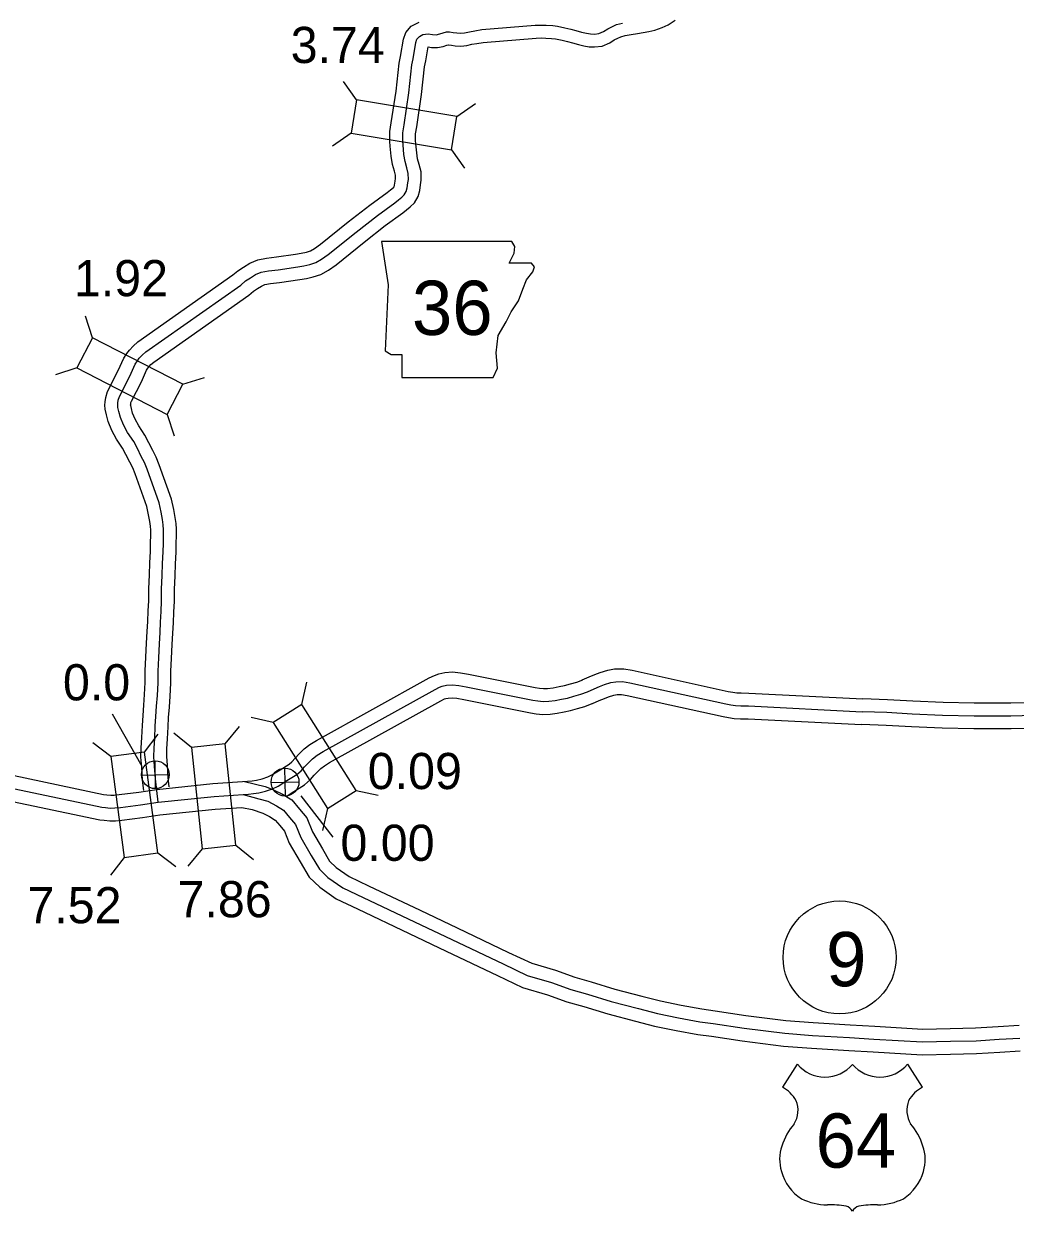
# Model space of a CAD drawing. Extents: x 31699 to 244310, y -8841 to 11474.
# Drawn here: x 104801 to 105573, y 1532 to 2457 of the extents above; entities that cross this region are included whole.
import ezdxf

# ---------------------------------------------------------------- set-up
doc = ezdxf.new("R2010")
doc.units = 0
for name, color, linetype in [('B_Logo', 7, 'Continuous'), ('G-ANNO-TEXT', 7, 'Continuous'), ('Level 21', 7, 'Continuous'), ('R_Border Notes', 7, 'Continuous'), ('R_XS_EARTHWORK_STAGE1', 7, 'Continuous'), ('R_XS_EARTHWORK_STAGE2', 7, 'Continuous'), ('S_AREA_CALC', 7, 'Continuous'), ('S_WALL', 7, 'Continuous'), ('S_WALL_ANNOT', 7, 'Continuous')]:
    doc.layers.add(name, color=color, linetype=linetype)

msp = doc.modelspace()

# ---------------------------------------------------------------- linework, layer by layer
for p, q in [((105403.81, 1646.97), (105392.27, 1629.12)), ((105489.6, 1646.97), (105501.14, 1629.12))]:
    msp.add_line(p, q)
for centre, radius, start, end in [((105425.3, 1665.05), 28.08, 220.07504, 319.67012), ((105468.11, 1665.05), 28.08, 220.32988, 319.92496), ((105377.19, 1603.22), 29.98, 30.7809, 59.98827), ((105516.22, 1603.22), 29.98, 120.01173, 149.2191), ((105383.79, 1611.13), 20.55, 328.81046, 21.21077), ((105509.62, 1611.13), 20.55, 158.78923, 211.18954), ((105437.53, 1569), 47.94, 138.95648, 162.69135), ((105455.88, 1569), 47.94, 17.30865, 41.04352), ((105421.7, 1572.93), 31.68, 160.95764, 197.38186), ((105471.71, 1572.93), 31.68, 342.61814, 19.04236), ((105426.86, 1573.02), 36.66, 195.10743, 237.13119), ((105466.55, 1573.02), 36.66, 302.86881, 344.89257), ((105427.54, 1584.56), 47.07, 244.07708, 269.57785), ((105428.63, 1451.29), 86.22, 81.19416, 90.95387), ((105439.41, 1528.59), 8.26, 28.03422, 72.98637), ((105454, 1528.59), 8.26, 107.01363, 151.96578), ((105464.78, 1451.29), 86.22, 89.04613, 98.80584), ((105465.87, 1584.56), 47.07, 270.42215, 295.92292)]:
    msp.add_arc(centre, radius, start, end)
at = {"layer": 'B_Logo'}
for points in [[(105104.56, 2429.93), (105106.77, 2442.67), (105107.65, 2445.16), (105109.55, 2447.34), (105112.32, 2448.8), (105116.25, 2449.21), (105119.67, 2448.75), (105122.61, 2448.67), (105125.53, 2449.27), (105128.12, 2450.12), (105130.71, 2450.78), (105132.91, 2450.82), (105135.93, 2450.42), (105138.61, 2450), (105141.55, 2449.73), (105144.68, 2450.12), (105148.41, 2451), (105152.6, 2451.69), (105158.06, 2452.6), (105199.79, 2455.99), (105204.27, 2456.14), (105208.28, 2455.96), (105213.42, 2455.79), (105217.11, 2455.2), (105222.81, 2454.11), (105227.51, 2453), (105231.34, 2451.88), (105235.77, 2450.76), (105239.59, 2449.9), (105242.81, 2449.3), (105245.75, 2449.16), (105249.29, 2449.5), (105252.92, 2451.17), (105256.29, 2453.32), (105259.79, 2455.13), (105263.1, 2456.53), (105267.55, 2457.69)], [(104906.21, 1850.99), (104903.93, 1869.2), (104903.35, 1879.02), (104902.75, 1886.3), (104902.95, 1892.98), (104903.41, 1900.88), (104903.83, 1910.25), (104904.29, 1917.74), (104904.87, 1925.71), (104905.52, 1934.14), (104906.07, 1943.84), (104906.03, 1953.14), (104906.5, 1963.44), (104907.03, 1974.34), (104907.53, 1983.24), (104907.98, 1991.14), (104908.36, 1999.44), (104908.81, 2007.67), (104908.76, 2016.96), (104909.3, 2027.66), (104909.59, 2036.89), (104910.02, 2045.93), (104910.16, 2052.55), (104910.38, 2058.97), (104910.36, 2063.18), (104910.09, 2066.98), (104909.55, 2071.19), (104908.44, 2076.92), (104906.84, 2084.11), (104897.61, 2110.22), (104895.38, 2115.52), (104892.95, 2120.3), (104889.9, 2126.32), (104887.07, 2131.82), (104882.33, 2138.96), (104879.15, 2144.85), (104876.71, 2150.69), (104875.56, 2155.15), (104874.76, 2158.48), (104874.67, 2160.08), (104874.77, 2161.75), (104875.06, 2164.17), (104875.87, 2166.99), (104884.04, 2182.84), (104888.27, 2192.08), (104889.89, 2194.64), (104891.39, 2196.68), (104893.54, 2198.99), (104896.5, 2201.58), (104970.55, 2253.69), (104974.22, 2256.9), (104977.91, 2259.37), (104981.93, 2261.91), (104986.43, 2263.66), (104992.08, 2264.83), (104999.47, 2265.63), (105014.77, 2267.77), (105019.62, 2268.73), (105024.27, 2269.75), (105028.78, 2271.23), (105033.33, 2273.85), (105038.6, 2277.55), (105060.28, 2294.98), (105076.84, 2307.98), (105090.46, 2317.78), (105093.15, 2320.03), (105095.92, 2322.15), (105097.75, 2323.92), (105099.24, 2326.49), (105099.98, 2329.38), (105100.58, 2333.2), (105100.99, 2336.01), (105100.84, 2340.62), (105099.75, 2345.01), (105098.33, 2349.87), (105097.49, 2355.4), (105096.75, 2362.81), (105096.5, 2365.81), (105096.51, 2368.76), (105096.51, 2372.37), (105097.53, 2378.47), (105101.33, 2403.27), (105103.65, 2425.1), (105104.56, 2429.93)], [(104972.19, 1857.1), (104976.32, 1857.38), (104980.45, 1857.72), (104984.57, 1858.33), (104989.75, 1859.69), (104995.12, 1861.32), (104999.48, 1863.47), (105006.34, 1867.8), (105013.98, 1872.48), (105017.46, 1875.55), (105020.07, 1878.67), (105023.08, 1881.73), (105026.22, 1884.86), (105029.97, 1887.67), (105034.52, 1890.49), (105121.72, 1938.89), (105125.15, 1940.56), (105127.34, 1941.4), (105130.59, 1942.06), (105135.19, 1942.41), (105140.13, 1941.89), (105145.96, 1940.86), (105197.77, 1930.48), (105201.72, 1929.81), (105205.86, 1929.41), (105210.33, 1929.56), (105215.18, 1930.31), (105220.3, 1931.21), (105224.82, 1932.09), (105229.86, 1933.65), (105235.17, 1935.01), (105240.33, 1937.04)], [(105240.33, 1937.04), (105245.62, 1939.41), (105249.79, 1941.15), (105253.57, 1942.62), (105258.61, 1944.12), (105262.46, 1944.79), (105267.8, 1944.88), (105273.28, 1943.91), (105348.02, 1927.51), (105351.97, 1926.85), (105355.65, 1926.24), (105359.92, 1926.05), (105365.79, 1926.02), (105454.39, 1921.48)], [(105596.82, 1918.73), (105570.13, 1918.02), (105541.42, 1918.02), (105516.97, 1918.61), (105493.18, 1919.68), (105473.45, 1920.74), (105454.39, 1921.48)], [(104779.51, 1864.47), (104862.13, 1847.14), (104865.14, 1846.86), (104868.81, 1846.46), (104872.28, 1846.52), (104876.81, 1846.93), (104892.44, 1849.01), (104906.21, 1850.99), (104949.61, 1855.57), (104972.19, 1857.1)], [(104972.19, 1857.1), (104984.6, 1853.61), (104991.45, 1851.68), (104998.19, 1848.3), (105003.69, 1844.88), (105008.42, 1839.21), (105013.16, 1833.53), (105017.21, 1823.47), (105025.33, 1809.58), (105031.6, 1798.86), (105038.27, 1792.49), (105049.79, 1784.45), (105065.63, 1776.92), (105105.74, 1757.84), (105134.76, 1744.04), (105174.7, 1725.05), (105193.38, 1716.16), (105212.32, 1710.63), (105227.51, 1705.15), (105240.38, 1701.48), (105258.87, 1695.86), (105280.25, 1690.3), (105294.99, 1686.46), (105311.37, 1683.07), (105327.94, 1680.1), (105338.3, 1678.65), (105362.32, 1675), (105393.99, 1671.09), (105415.5, 1669.45), (105444.44, 1667.76), (105463.46, 1666.49), (105501.29, 1664.35), (105522.96, 1664.79), (105542.98, 1665.19), (105560.92, 1666.38), (105577.01, 1667.32)]]:
    msp.add_lwpolyline(points, dxfattribs=at)
at = {"layer": 'G-ANNO-TEXT'}
msp.add_lwpolyline([(105080.08, 2287.65), (105085.16, 2253.82), (105082.9, 2202.5), (105087.41, 2199.68), (105095.87, 2199.68), (105095.87, 2181.64), (105166.92, 2181.64), (105170.31, 2188.97), (105169.18, 2200.81), (105170.87, 2214.34), (105177.08, 2225.06), (105181.02, 2232.95), (105186.66, 2241.41), (105190.05, 2250.44), (105192.87, 2257.77), (105197.94, 2263.97), (105199.07, 2267.92), (105196.81, 2270.74), (105179.33, 2270.74), (105183.28, 2278.63), (105183.84, 2283.71), (105181.5, 2287.6)], close=True, dxfattribs=at)
at = {"layer": 'Level 21'}
for p, q in [((104904.15, 1861.55), (104903.65, 1883.25)), ((105005.15, 1855.82), (105004.65, 1877.52)), ((104893.05, 1872.15), (104914.75, 1872.65)), ((104994.05, 1866.42), (105015.75, 1866.92))]:
    msp.add_line(p, q, dxfattribs=at)
for centre in [(104903.9, 1872.4), (105004.9, 1866.67)]:
    msp.add_circle(centre, 10.85, dxfattribs=at)
at = {"layer": 'R_Border Notes'}
msp.add_circle((105436.73, 1730.17), 44, dxfattribs=at)
at = {"layer": 'R_XS_EARTHWORK_STAGE1'}
for p, q in [((105060.64, 2398.01), (105050.42, 2412.34)), ((105138.76, 2384.96), (105153.09, 2395.19)), ((105056.29, 2371.97), (105041.97, 2361.75)), ((105134.41, 2358.92), (105144.63, 2344.6)), ((104854.89, 2212.72), (104849.53, 2229.48)), ((104842.8, 2189.25), (104826.03, 2183.89)), ((104925.29, 2176.43), (104942.05, 2181.79)), ((104913.19, 2152.96), (104918.55, 2136.2)), ((105017.88, 1927.19), (105021.76, 1944.36)), ((104995.57, 1913.08), (104978.4, 1916.95)), ((104958.33, 1896.34), (104969.4, 1910.02)), ((104869.29, 1886.56), (104855.31, 1897.25)), ((104895.46, 1890.04), (104906.15, 1904.02)), ((104932.08, 1893.57), (104918.39, 1904.64)), ((105060.2, 1860.24), (105077.37, 1856.37)), ((105037.88, 1846.13), (105034.01, 1828.97)), ((104940.38, 1814.8), (104929.31, 1801.12)), ((104966.64, 1817.57), (104980.32, 1806.5)), ((104879.74, 1808.05), (104869.04, 1794.07)), ((104905.9, 1811.54), (104919.88, 1800.84))]:
    msp.add_line(p, q, dxfattribs=at)
for points in [[(105056.29, 2371.97), (105134.41, 2358.92), (105138.76, 2384.96), (105060.64, 2398.01)], [(104842.8, 2189.25), (104913.19, 2152.96), (104925.29, 2176.43), (104854.89, 2212.72)], [(104995.57, 1913.08), (105037.88, 1846.13), (105060.2, 1860.24), (105017.88, 1927.19)], [(104932.08, 1893.57), (104940.38, 1814.8), (104966.64, 1817.57), (104958.33, 1896.34)], [(104869.29, 1886.56), (104879.74, 1808.05), (104905.9, 1811.54), (104895.46, 1890.04)]]:
    msp.add_lwpolyline(points, close=True, dxfattribs=at)
at = {"layer": 'R_XS_EARTHWORK_STAGE2'}
for points in [[(105207.89, 2445.97), (105212.46, 2445.82), (105215.37, 2445.35), (105220.72, 2444.33), (105224.95, 2443.33), (105228.71, 2442.23), (105233.45, 2441.03), (105237.57, 2440.11), (105241.64, 2439.34), (105245.99, 2439.13), (105251.93, 2439.7), (105257.73, 2442.38), (105261.28, 2444.64), (105264.04, 2446.07), (105266.33, 2447.04), (105269.67, 2447.91), (105274.37, 2448.73), (105279.36, 2449.51), (105283.84, 2450.35), (105288.29, 2451.13), (105292.91, 2452.12), (105298.63, 2454.16), (105303.21, 2456.39), (105308.57, 2460.04)], [(104895, 1860.09), (104893.97, 1868.28), (104893.37, 1878.31), (104892.73, 1886.04), (104892.96, 1893.43), (104893.42, 1901.39), (104893.85, 1910.78), (104894.31, 1918.41), (104894.9, 1926.45), (104895.54, 1934.8), (104896.07, 1944.11), (104896.03, 1953.34), (104896.51, 1963.91), (104897.04, 1974.87), (104897.55, 1983.81), (104897.99, 1991.65), (104898.37, 1999.93), (104898.8, 2007.92), (104898.76, 2017.18), (104899.31, 2028.07), (104899.6, 2037.29), (104900.03, 2046.27), (104900.17, 2052.82), (104900.38, 2059.12), (104900.37, 2062.81), (104900.14, 2065.98), (104899.67, 2069.59), (104898.65, 2074.88), (104897.21, 2081.34), (104888.28, 2106.61), (104886.3, 2111.32), (104884.03, 2115.77), (104881, 2121.78), (104878.43, 2126.75), (104873.75, 2133.81), (104870.12, 2140.54), (104867.21, 2147.5), (104865.85, 2152.74), (104864.83, 2157), (104864.65, 2160.08), (104864.8, 2162.65), (104865.22, 2166.16), (104866.53, 2170.7), (104875.05, 2187.22), (104879.46, 2196.84), (104881.62, 2200.28), (104883.68, 2203.07), (104886.57, 2206.17), (104890.3, 2209.45), (104964.37, 2261.57), (104968.13, 2264.85), (104972.45, 2267.75), (104977.4, 2270.88), (104983.59, 2273.29), (104990.53, 2274.72), (104998.24, 2275.56), (105013.11, 2277.64), (105017.58, 2278.52), (105021.63, 2279.41), (105024.68, 2280.41), (105027.95, 2282.29), (105032.58, 2285.55), (105054.06, 2302.81), (105070.83, 2315.97), (105084.32, 2325.68), (105086.9, 2327.83), (105089.38, 2329.74), (105089.8, 2330.14), (105089.9, 2330.31), (105090.18, 2331.4), (105090.69, 2334.69), (105090.97, 2336.58), (105090.88, 2339.24), (105090.1, 2342.41), (105088.54, 2347.7), (105087.57, 2354.16), (105086.8, 2361.89), (105086.49, 2365.41), (105086.51, 2368.77), (105086.51, 2373.19), (105087.65, 2380.05), (105091.41, 2404.56), (105093.75, 2426.56), (105094.71, 2431.64), (105097.06, 2445.21), (105098.86, 2450.29), (105103.23, 2455.31), (105109.36, 2458.54)], [(104914.79, 1862.97), (104913.9, 1870.12), (104913.33, 1879.73), (104912.76, 1886.55), (104912.95, 1892.54), (104913.39, 1900.37), (104913.82, 1909.71), (104914.27, 1917.07), (104914.85, 1924.96), (104915.5, 1933.48), (104916.07, 1943.58), (104916.03, 1952.93), (104916.49, 1962.97), (104917.02, 1973.82), (104917.51, 1982.68), (104917.97, 1990.63), (104918.35, 1998.94), (104918.81, 2007.42), (104918.77, 2016.73), (104919.29, 2027.26), (104919.58, 2036.5), (104920.02, 2045.58), (104920.16, 2052.27), (104920.38, 2058.82), (104920.36, 2063.55), (104920.05, 2067.99), (104919.42, 2072.78), (104918.23, 2078.95), (104916.47, 2086.87), (104906.94, 2113.82), (104904.45, 2119.73), (104901.87, 2124.82), (104898.81, 2130.87), (104895.7, 2136.9), (104890.92, 2144.11), (104888.19, 2149.17), (104886.21, 2153.89), (104885.26, 2157.56), (104884.69, 2159.95), (104884.68, 2160.08), (104884.73, 2160.86), (104884.89, 2162.17), (104885.21, 2163.28), (104893.04, 2178.47), (104897.09, 2187.31), (104898.16, 2189.01), (104899.09, 2190.28), (104900.51, 2191.8), (104902.69, 2193.71), (104976.73, 2245.81), (104980.32, 2248.95), (104983.37, 2250.99), (104986.46, 2252.95), (104989.28, 2254.04), (104993.64, 2254.94), (105000.7, 2255.71), (105016.43, 2257.91), (105021.65, 2258.94), (105026.91, 2260.09), (105032.88, 2262.05), (105038.71, 2265.41), (105044.61, 2269.56), (105066.5, 2287.15), (105082.85, 2299.98), (105096.6, 2309.87), (105099.41, 2312.23), (105102.45, 2314.56), (105105.7, 2317.7), (105108.58, 2322.66), (105109.79, 2327.35), (105110.46, 2331.7), (105111.02, 2335.45), (105110.8, 2342), (105109.41, 2347.62), (105108.12, 2352.04), (105107.42, 2356.65), (105106.71, 2363.73), (105106.5, 2366.22), (105106.51, 2368.74), (105106.51, 2371.54), (105107.4, 2376.88), (105111.25, 2401.98), (105113.56, 2423.64), (105114.42, 2428.22), (105116.3, 2439.12), (105118.86, 2438.77), (105123.49, 2438.65), (105128.11, 2439.59), (105130.92, 2440.52), (105132.05, 2440.8), (105132.34, 2440.81), (105134.5, 2440.52), (105137.38, 2440.07), (105141.72, 2439.67), (105146.47, 2440.27), (105150.36, 2441.19), (105154.23, 2441.82), (105159.29, 2442.67), (105200.38, 2446), (105204.21, 2446.14), (105207.89, 2445.97)]]:
    msp.add_lwpolyline(points, dxfattribs=at)
at = {"layer": 'S_AREA_CALC'}
for points in [[(104781.48, 1874.27), (104863.63, 1857.04), (104866.15, 1856.81), (104869.27, 1856.47), (104871.74, 1856.51), (104875.69, 1856.87), (104891.07, 1858.92), (104904.97, 1860.92), (104948.75, 1865.53), (104975.57, 1867.35), (104979.31, 1867.66), (104982.57, 1868.14), (104987.02, 1869.31), (104991.43, 1870.65), (104994.59, 1872.21), (105001.05, 1876.29), (105008.02, 1880.56), (105010.28, 1882.55), (105012.66, 1885.4), (105015.99, 1888.78), (105019.67, 1892.45), (105024.33, 1895.94), (105029.46, 1899.12), (105117.11, 1947.77), (105121.17, 1949.74), (105124.53, 1951.03), (105129.22, 1951.98), (105135.33, 1952.45), (105141.53, 1951.8), (105147.81, 1950.68), (105199.59, 1940.31), (105203.03, 1939.73), (105206.17, 1939.43), (105209.39, 1939.54), (105213.56, 1940.18), (105218.48, 1941.04), (105222.38, 1941.8), (105227.14, 1943.27), (105232.08, 1944.54), (105236.68, 1946.35)], [(105236.25, 1946.17), (105241.65, 1948.59), (105246.05, 1950.43), (105250.33, 1952.09), (105256.33, 1953.87), (105261.51, 1954.77), (105268.59, 1954.9), (105275.23, 1953.72), (105349.93, 1937.33), (105353.61, 1936.71), (105356.69, 1936.21), (105360.17, 1936.05), (105366.07, 1936.02), (105454.9, 1931.46)], [(105244.42, 1927.91), (105249.6, 1930.23), (105253.54, 1931.88), (105256.81, 1933.15), (105260.89, 1934.36), (105263.41, 1934.8), (105267.01, 1934.86), (105271.34, 1934.1), (105346.12, 1917.69), (105350.33, 1916.98), (105354.61, 1916.28), (105359.67, 1916.05), (105365.51, 1916.02), (105453.88, 1911.49)], [(105005.66, 1855.55), (105011.62, 1859.31), (105019.95, 1864.41), (105024.65, 1868.56), (105027.48, 1871.95), (105030.18, 1874.69), (105032.78, 1877.28), (105035.62, 1879.4), (105039.59, 1881.87), (105126.33, 1930.01), (105129.14, 1931.38), (105130.15, 1931.76), (105131.97, 1932.13), (105135.05, 1932.37), (105138.74, 1931.98), (105144.1, 1931.03), (105195.96, 1920.64), (105200.41, 1919.89), (105205.55, 1919.4), (105211.26, 1919.59), (105216.81, 1920.45), (105222.12, 1921.37), (105227.26, 1922.38), (105232.58, 1924.02), (105238.25, 1925.48), (105243.99, 1927.74)], [(105596.53, 1928.72), (105569.99, 1928.02), (105541.54, 1928.02), (105517.32, 1928.61), (105493.67, 1929.67), (105473.91, 1930.73), (105454.77, 1931.47)], [(105597.11, 1908.73), (105570.26, 1908.02), (105541.3, 1908.02), (105516.62, 1908.62), (105492.68, 1909.69), (105472.99, 1910.75), (105454, 1911.48)], [(104973.33, 1867.17), (104989.46, 1863.12), (104995.28, 1860.99), (105002.99, 1857.22), (105010.17, 1852.72), (105016.1, 1845.62), (105021.85, 1838.73), (105026.21, 1827.88), (105033.96, 1814.63), (105039.53, 1805.12), (105044.62, 1800.25), (105054.83, 1793.13), (105069.92, 1785.95), (105110.03, 1766.87), (105139.05, 1753.07), (105179, 1734.08), (105196.95, 1725.54), (105215.42, 1720.15), (105230.58, 1714.68), (105243.21, 1711.08), (105261.59, 1705.49), (105282.77, 1699.98), (105297.26, 1696.2), (105313.26, 1692.89), (105329.52, 1689.97), (105339.74, 1688.55), (105363.69, 1684.91), (105394.98, 1681.04), (105416.17, 1679.43), (105445.07, 1677.74), (105464.08, 1676.47), (105501.47, 1674.36), (105522.76, 1674.79), (105542.55, 1675.18), (105560.3, 1676.36), (105576.62, 1677.31)], [(104777.53, 1854.66), (104860.63, 1837.24), (104864.13, 1836.91), (104868.36, 1836.45), (104872.83, 1836.53), (104877.92, 1836.99), (104893.81, 1839.11), (104907.45, 1841.07), (104950.47, 1845.61), (104971.14, 1847)], [(104971.14, 1847), (104979.19, 1845.27), (104987.62, 1842.37), (104992.8, 1839.8), (104997.2, 1837.04), (105000.75, 1832.8), (105004.47, 1828.34), (105008.2, 1819.06), (105016.7, 1804.53), (105023.68, 1792.6), (105031.91, 1784.73), (105044.74, 1775.78), (105061.34, 1767.89), (105101.45, 1748.81), (105130.46, 1735.01), (105170.41, 1716.02), (105189.81, 1706.79), (105209.22, 1701.12), (105224.43, 1695.63), (105237.56, 1691.89), (105256.16, 1686.24), (105277.73, 1680.62), (105292.71, 1676.72), (105309.47, 1673.25), (105326.37, 1670.22), (105336.86, 1668.76), (105360.96, 1665.09), (105393, 1661.14), (105414.83, 1659.48), (105443.81, 1657.78), (105462.85, 1656.51), (105501.11, 1654.35), (105523.16, 1654.79), (105543.41, 1655.2), (105561.55, 1656.4), (105577.4, 1657.33)]]:
    msp.add_lwpolyline(points, dxfattribs=at)
at = {"layer": 'S_WALL'}
msp.add_lwpolyline([(105042.31, 1823.71), (105017.4, 1856.04)], dxfattribs=at)
at = {"layer": 'S_WALL_ANNOT'}
msp.add_line((104870.24, 1919.7), (104893.49, 1879.02), dxfattribs=at)

# ---------------------------------------------------------------- texts
msp.add_text('64', height=42.24).set_placement((105418.03, 1566.41))
at = {"layer": 'G-ANNO-TEXT'}
msp.add_text('36', height=42.24, dxfattribs=at).set_placement((105103.72, 2214.85))
at = {"layer": 'R_Border Notes'}
msp.add_text('9', height=42.24, dxfattribs=at).set_placement((105426.18, 1707.7))
at = {"layer": 'S_WALL'}
for s, p in [('3.74', (105009.28, 2426.61)), ('1.92', (104840.45, 2245.02)), ('0.09', (105069.31, 1861.22)), ('0.00', (105048.06, 1805.32)), ('7.52', (104804.26, 1756.75)), ('7.86', (104921.19, 1761.42))]:
    msp.add_text(s, height=28.16, dxfattribs=at).set_placement(p)
at = {"layer": 'S_WALL_ANNOT'}
msp.add_text('0.0', height=28.16, dxfattribs=at).set_placement((104831.94, 1930.32))

doc.saveas('drawing.dxf')
